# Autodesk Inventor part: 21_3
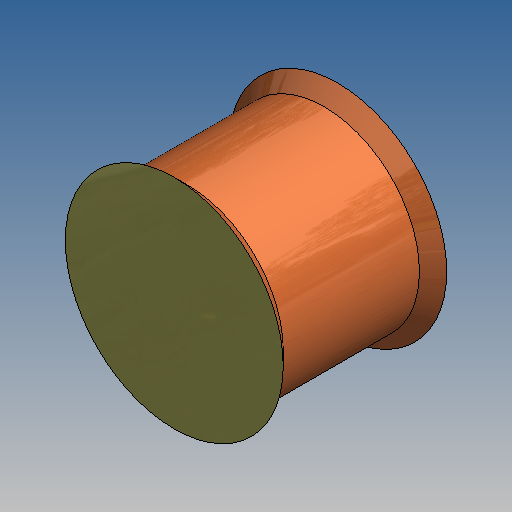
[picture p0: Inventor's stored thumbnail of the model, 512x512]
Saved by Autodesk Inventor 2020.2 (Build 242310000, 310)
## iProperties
Part Number: 21_3
Material: Generic
Document SubType Name: Modeling
Designer: amoles
Appearance: Default
Author: amoles
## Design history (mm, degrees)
feature "Base1"
body "Solid1"
